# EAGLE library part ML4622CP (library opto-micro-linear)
FIBER OPTIC DATA QUANTIZER
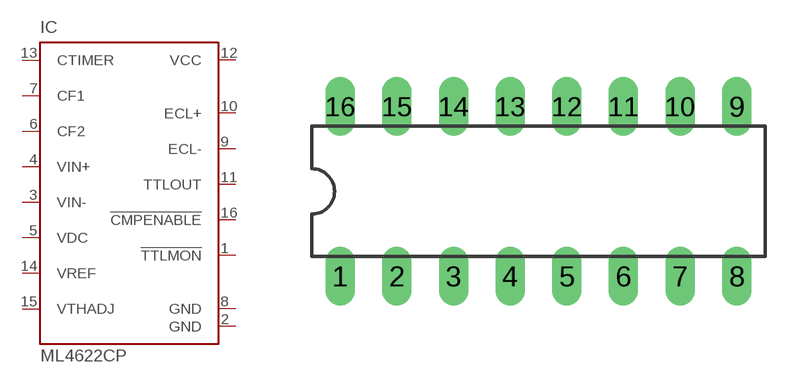
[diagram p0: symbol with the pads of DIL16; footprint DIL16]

Designator prefix IC

## ML4622CP (OC_FARNELL: unknown; OC_NEWARK: unknown)  [DIL16]
1  !TTLMON  out
2  GND  pwr
3  VIN-  in
4  VIN+  in
5  VDC  pas
6  CF2  pas
7  CF1  pas
8  GND  pwr
9  ECL-  out
10  ECL+  out
11  TTLOUT  out
12  VCC  pwr
13  CTIMER  pas
14  VREF  in
15  VTHADJ  in
16  !CMPENABLE  in

## Footprint DIL16 (pad centres in mm)
Dual In Line Package
drill 0.813 long: 1 -8.89,-3.81; 2 -6.35,-3.81; 3 -3.81,-3.81; 4 -1.27,-3.81; 5 1.27,-3.81; 6 3.81,-3.81; 7 6.35,-3.81; 8 8.89,-3.81; 9 8.89,3.81; 10 6.35,3.81; 11 3.81,3.81; 12 1.27,3.81; 13 -1.27,3.81; 14 -3.81,3.81; 15 -6.35,3.81; 16 -8.89,3.81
